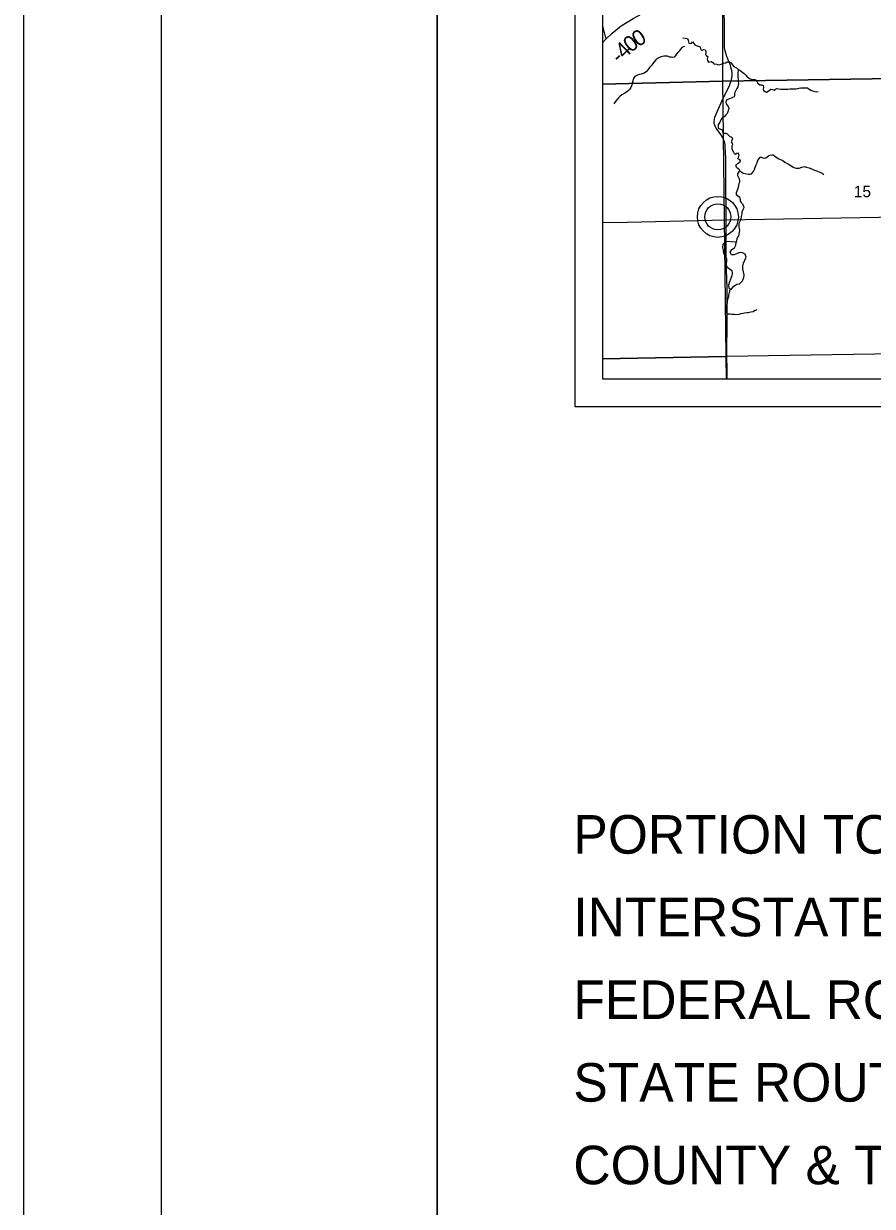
# Model space of a CAD drawing. Extents: x 0 to 34, y 0 to 22.
# Drawn here: x 0 to 3.079, y 11.097 to 15.389 of the extents above; entities that cross this region are included whole.
import ezdxf

# ---------------------------------------------------------------- set-up
doc = ezdxf.new("R2010")
doc.units = 0
for name, color, linetype in [('Default', 7, 'Continuous'), ('GM_X_County_Road', 7, 'Continuous'), ('GM_X_County_Road_Text', 7, 'Continuous'), ('GM_X_Minor_River', 7, 'Continuous'), ('GM_X_Rail_Line', 7, 'Continuous'), ('GM_X_Section', 7, 'Continuous'), ('GM_X_Section_Text', 7, 'Continuous'), ('GM_X_Township_Road', 7, 'Continuous'), ('GM_X_Unincorporated', 7, 'Continuous'), ('GM_X_Unincorporated_Location', 7, 'Continuous'), ('SH_Border', 7, 'Continuous'), ('SH_Cut_Line', 7, 'Continuous'), ('SH_Data', 7, 'Continuous'), ('SH_Text', 7, 'Continuous')]:
    doc.layers.add(name, color=color, linetype=linetype)

msp = doc.modelspace()

# ---------------------------------------------------------------- linework, layer by layer
at = {"layer": 'Default'}
for points in [[(2.1, 16.1599), (2.1, 15.1701), (2.5373, 15.181), (2.5362, 16.1651)], [(2.1, 15.1701), (2.1, 14.1728), (2.5493, 14.1808), (2.5373, 15.181)], [(2.1, 14.1728), (2.1, 14.1), (2.5497, 14.1), (2.5493, 14.1808)], [(2.5497, 14.1), (3.5508, 14.1), (3.5507, 14.1966), (2.5493, 14.1808)]]:
    msp.add_lwpolyline(points, close=True, dxfattribs=at)
at = {"layer": 'GM_X_County_Road'}
msp.add_lwpolyline([(2.1, 15.32), (2.1122, 15.3327), (2.1348, 15.3546), (2.1678, 15.3816), (2.2117, 15.4084), (2.3211, 15.4672), (2.3828, 15.501), (2.4511, 15.5376), (2.4613, 15.5442), (2.4683, 15.5476), (2.4745, 15.5517), (2.4853, 15.5591), (2.4974, 15.5707), (2.5116, 15.5851)], dxfattribs=at)
at = {"layer": 'GM_X_Minor_River'}
for points in [[(2.3917, 15.3375), (2.4089, 15.3348), (2.4116, 15.3295), (2.4117, 15.3238), (2.4134, 15.3185), (2.4183, 15.3171), (2.4232, 15.3184), (2.4273, 15.3234), (2.432, 15.3178), (2.4351, 15.3122), (2.4401, 15.3096), (2.447, 15.3071), (2.4531, 15.3068), (2.4559, 15.2997), (2.4572, 15.2944), (2.4621, 15.293), (2.4674, 15.295), (2.4731, 15.294), (2.4751, 15.2891), (2.4748, 15.2838), (2.4742, 15.2788), (2.4769, 15.2739), (2.482, 15.2706), (2.4813, 15.2653), (2.4803, 15.2603), (2.4811, 15.2554), (2.4847, 15.2498), (2.4896, 15.2503), (2.4949, 15.2515), (2.4999, 15.2486), (2.5038, 15.243), (2.5148, 15.2417), (2.5202, 15.2403), (2.5266, 15.2408), (2.5349, 15.2436), (2.5402, 15.2453), (2.5474, 15.2473), (2.553, 15.2501), (2.5602, 15.251), (2.5671, 15.2473), (2.5706, 15.2413), (2.5745, 15.2361), (2.5815, 15.2313), (2.5865, 15.2291), (2.593, 15.2232), (2.5984, 15.2199), (2.6049, 15.2162), (2.6146, 15.2081), (2.6208, 15.2021), (2.6251, 15.1961), (2.634, 15.1902), (2.6424, 15.1866), (2.6473, 15.186), (2.653, 15.1865), (2.658, 15.1843), (2.6643, 15.173), (2.6713, 15.1671), (2.6781, 15.1672), (2.6835, 15.1643), (2.6844, 15.1575), (2.6837, 15.1518), (2.6846, 15.1465), (2.69, 15.1432), (2.695, 15.141), (2.701, 15.1438), (2.7066, 15.1477), (2.7115, 15.1516), (2.7168, 15.1498), (2.7229, 15.1484), (2.7278, 15.1512), (2.7327, 15.1536), (2.7403, 15.1526), (2.746, 15.1516), (2.7543, 15.1518), (2.7597, 15.1515), (2.7729, 15.1518), (2.7794, 15.1523), (2.7877, 15.1521), (2.7972, 15.1527), (2.8025, 15.1531), (2.8124, 15.1549), (2.8192, 15.1558), (2.8264, 15.1559), (2.8313, 15.1564), (2.8385, 15.1566), (2.8442, 15.1559), (2.8504, 15.1519), (2.8562, 15.1482), (2.8619, 15.1453), (2.8669, 15.1439), (2.8779, 15.1418), (2.8828, 15.1427)], [(2.3979, 15.3064), (2.3935, 15.3056), (2.3883, 15.3028), (2.3838, 15.2974), (2.3801, 15.2924), (2.3772, 15.2874), (2.3716, 15.282), (2.3661, 15.2746), (2.3605, 15.2677), (2.3545, 15.266), (2.3495, 15.2671), (2.3427, 15.2681), (2.3358, 15.271), (2.3293, 15.2712), (2.3225, 15.2707), (2.3176, 15.2698), (2.3119, 15.2686), (2.3048, 15.2657), (2.2995, 15.2626), (2.2939, 15.2583), (2.2832, 15.2444), (2.278, 15.2375), (2.271, 15.2297), (2.2651, 15.2216), (2.2599, 15.2158), (2.2509, 15.2099), (2.24, 15.2055), (2.2347, 15.2043), (2.2268, 15.2022), (2.2174, 15.1974), (2.2122, 15.1901), (2.2095, 15.1779), (2.2081, 15.171), (2.2052, 15.163), (2.203, 15.1576), (2.199, 15.1518), (2.1942, 15.1464), (2.1875, 15.1402), (2.1815, 15.1367), (2.1702, 15.1311), (2.1631, 15.1253), (2.1587, 15.1195), (2.1524, 15.1129), (2.1464, 15.1055), (2.1409, 15.0978)], [(2.593, 15.2232), (2.5914, 15.2083), (2.5912, 15.2007), (2.591, 15.195), (2.5919, 15.1878), (2.5928, 15.1795), (2.5934, 15.1719), (2.5927, 15.1658), (2.591, 15.1597), (2.5873, 15.1543), (2.5793, 15.1374), (2.5787, 15.1287), (2.5773, 15.1233), (2.5724, 15.121), (2.5671, 15.119), (2.5551, 15.1138), (2.5491, 15.1102), (2.5477, 15.1041), (2.549, 15.0984), (2.5521, 15.0932), (2.5556, 15.0883), (2.5584, 15.0815), (2.5578, 15.0766), (2.5549, 15.0693), (2.5527, 15.0632), (2.5479, 15.0582), (2.542, 15.0516), (2.533, 15.0461), (2.5293, 15.0403), (2.5275, 15.0346), (2.5235, 15.0284), (2.5198, 15.0215), (2.5196, 15.0154), (2.5201, 15.0097), (2.5285, 15.0065), (2.5339, 15.0047), (2.5352, 14.9948), (2.5413, 14.9919), (2.5478, 14.9913), (2.5528, 14.9899), (2.5625, 14.9798), (2.5674, 14.9784), (2.5713, 14.9732), (2.5696, 14.9656), (2.5667, 14.9602), (2.5706, 14.9546), (2.5718, 14.9497), (2.57, 14.9447), (2.569, 14.9397), (2.5691, 14.9344), (2.5715, 14.9291), (2.575, 14.9231), (2.5774, 14.9175), (2.5824, 14.9153), (2.5873, 14.9196), (2.5922, 14.9201), (2.5938, 14.9144), (2.5943, 14.9095), (2.5925, 14.9045), (2.5907, 14.8992), (2.5965, 14.8974), (2.5993, 14.891), (2.5982, 14.886), (2.5926, 14.8821), (2.5844, 14.8774), (2.5841, 14.8709), (2.5888, 14.8657), (2.5946, 14.862), (2.5977, 14.8568), (2.5944, 14.8514), (2.5904, 14.8441), (2.5901, 14.8384), (2.5941, 14.8305), (2.5961, 14.8256), (2.597, 14.8195), (2.5967, 14.8142), (2.5953, 14.8092), (2.5925, 14.7959), (2.5904, 14.7879), (2.5875, 14.7813), (2.5854, 14.7752), (2.5851, 14.7695), (2.5905, 14.7655), (2.5967, 14.7599), (2.5992, 14.7508), (2.6, 14.7455), (2.6032, 14.7399), (2.6086, 14.7354), (2.6122, 14.7264), (2.6127, 14.7211), (2.6087, 14.7111), (2.6062, 14.7043), (2.6052, 14.6989), (2.6049, 14.694), (2.6039, 14.689), (2.6025, 14.6814), (2.5997, 14.6733), (2.5949, 14.6641), (2.5947, 14.6565), (2.5948, 14.6508), (2.5964, 14.6459)], [(2.5977, 14.8568), (2.6104, 14.8472), (2.6184, 14.8454), (2.6291, 14.8434), (2.6356, 14.8424), (2.6405, 14.8444), (2.6479, 14.8529), (2.6515, 14.8602), (2.6536, 14.8682), (2.658, 14.8766), (2.6609, 14.8843), (2.6627, 14.8897), (2.6663, 14.8962), (2.6718, 14.905), (2.6768, 14.9051), (2.6825, 14.9018), (2.6875, 14.9008), (2.6924, 14.9024), (2.7025, 14.9095), (2.7074, 14.9119), (2.7142, 14.9131), (2.7195, 14.9129), (2.7299, 14.9047), (2.7399, 14.8981), (2.7457, 14.8963), (2.7549, 14.892), (2.7622, 14.8864), (2.7699, 14.8813), (2.7776, 14.8776), (2.7833, 14.8743), (2.7918, 14.8684), (2.7983, 14.8655), (2.8033, 14.8645), (2.8086, 14.8646), (2.8139, 14.8651), (2.8229, 14.8683), (2.8286, 14.87), (2.8347, 14.8705), (2.8396, 14.8687), (2.8503, 14.8655), (2.8695, 14.8575), (2.8802, 14.8536), (2.8917, 14.8489), (2.8974, 14.846), (2.9036, 14.8423)], [(2.5964, 14.6459), (2.597, 14.6387), (2.596, 14.6319), (2.5932, 14.6189), (2.5903, 14.6139), (2.5874, 14.6085), (2.5851, 14.5956)], [(2.5834, 14.5961), (2.5459, 14.5989), (2.5367, 14.588), (2.5359, 14.5774), (2.5374, 14.5671), (2.5392, 14.5565), (2.5452, 14.5469), (2.5505, 14.5374), (2.5504, 14.5279), (2.5492, 14.5173), (2.5499, 14.5078), (2.5597, 14.5005), (2.57, 14.4932), (2.571, 14.4837), (2.5698, 14.4743), (2.5644, 14.4622), (2.5605, 14.4519), (2.5574, 14.4406), (2.5581, 14.43), (2.5676, 14.4246), (2.5764, 14.4363), (2.5879, 14.4438)], [(2.5879, 14.4438), (2.5974, 14.4448), (2.6081, 14.4561), (2.6124, 14.4675), (2.614, 14.4773), (2.6099, 14.4994), (2.6096, 14.5092), (2.6116, 14.5199), (2.617, 14.5308), (2.6209, 14.5422), (2.6179, 14.5528), (2.608, 14.5575), (2.5985, 14.5583), (2.5886, 14.5549), (2.5783, 14.5497), (2.5684, 14.5498), (2.5639, 14.5593), (2.5697, 14.5691), (2.5793, 14.5759), (2.5843, 14.5857), (2.5851, 14.5956), (2.5834, 14.5961)], [(2.5631, 14.4265), (2.561, 14.4191), (2.5572, 14.4031), (2.5569, 14.3977), (2.5544, 14.3916), (2.553, 14.3828), (2.5528, 14.376), (2.5499, 14.368), (2.5489, 14.3626), (2.5486, 14.3569), (2.5489, 14.3448), (2.5505, 14.3387), (2.5555, 14.3365), (2.5631, 14.3359), (2.5692, 14.3349), (2.5791, 14.3348), (2.5841, 14.3341), (2.5958, 14.3351), (2.6037, 14.3372), (2.6105, 14.3385), (2.6154, 14.3397), (2.6238, 14.3406), (2.6291, 14.3408), (2.6385, 14.3429), (2.6472, 14.3449), (2.6521, 14.3481), (2.657, 14.3493), (2.6619, 14.3517)]]:
    msp.add_lwpolyline(points, dxfattribs=at)
at = {"layer": 'GM_X_Rail_Line'}
msp.add_lwpolyline([(2.1, 17.2107), (2.1, 14.1), (5.5619, 14.1), (5.5608, 14.205), (5.5615, 14.2414), (5.5595, 14.6439), (5.5583, 14.9347), (5.5581, 14.9676), (5.5588, 15.1747), (5.5579, 15.2049), (4.0847, 15.1965), (3.5411, 15.1931), (3.5298, 15.9318), (3.5269, 16.3549), (3.511, 17.2267), (3.4711, 17.2262), (2.9494, 17.2203), (2.5218, 17.2155)], close=True, dxfattribs=at)
at = {"layer": 'GM_X_Section'}
for points in [[(2.5362, 16.1651), (3.5333, 16.1865), (3.5436, 15.1965), (2.5373, 15.181)], [(2.5373, 15.181), (3.5436, 15.1965), (3.5507, 14.1966), (2.5493, 14.1808)]]:
    msp.add_lwpolyline(points, close=True, dxfattribs=at)
at = {"layer": 'GM_X_Township_Road'}
for points in [[(2.5096, 15.015), (2.5073, 15.0203), (2.5058, 15.0274), (2.5054, 15.0335), (2.5063, 15.0423), (2.5077, 15.0497), (2.5113, 15.0585), (2.5384, 15.1183), (2.5605, 15.1635), (2.5651, 15.1753), (2.5674, 15.1822), (2.5696, 15.192), (2.5708, 15.2025), (2.5708, 15.2105), (2.5689, 15.2189), (2.5672, 15.2262), (2.5646, 15.2372), (2.5617, 15.2444), (2.5591, 15.252), (2.5553, 15.262), (2.5517, 15.27), (2.5475, 15.2824), (2.5448, 15.2907), (2.543, 15.3015), (2.5423, 15.3193), (2.5434, 15.3652), (2.541, 15.5446)], [(2.1, 15.3803), (2.1008, 15.3771), (2.1122, 15.3327)], [(2.1, 14.6671), (2.19, 14.6684), (2.5484, 14.6774), (3.1035, 14.6866), (3.1904, 14.6884), (3.5595, 14.6939), (3.8262, 14.9464), (3.8356, 14.9553), (3.8461, 14.9638), (3.855, 14.9715), (3.8812, 14.9962), (3.8946, 15.0105), (3.9125, 15.0298), (3.9618, 15.0811), (3.9775, 15.0976), (4.0171, 15.1332), (4.0644, 15.171)], [(2.5484, 14.6774), (2.5479, 14.8271), (2.5482, 14.8961), (2.5468, 14.9267), (2.5458, 14.94), (2.5448, 14.9486), (2.5436, 14.9567), (2.5425, 14.962), (2.5404, 14.9669), (2.5384, 14.9719), (2.5356, 14.9776), (2.532, 14.9838), (2.5275, 14.9907), (2.5184, 15.0015), (2.5125, 15.0098), (2.5096, 15.015)], [(2.5524, 14.1), (2.5524, 14.1102), (2.5524, 14.1375), (2.5512, 14.1776), (2.5528, 14.32), (2.552, 14.4291), (2.5504, 14.4961), (2.5488, 14.5755), (2.5484, 14.6774)]]:
    msp.add_lwpolyline(points, dxfattribs=at)
at = {"layer": 'GM_X_Unincorporated'}
for radius in [0.0744, 0.0472]:
    msp.add_circle((2.5187, 14.6881), radius, dxfattribs=at)
at = {"layer": 'GM_X_Unincorporated_Location'}
msp.add_line((2.5187, 14.6881), (2.5187, 14.6881), dxfattribs=at)
at = {"layer": 'SH_Border'}
for points in [[(0.5, 21.5), (1.5, 21.5), (1.5, 0.5), (0.5, 0.5)], [(1.5, 21.5), (33.5, 21.5), (33.5, 0.5), (1.5, 0.5)]]:
    msp.add_lwpolyline(points, close=True, dxfattribs=at)
at = {"layer": 'SH_Cut_Line'}
msp.add_lwpolyline([(0, 0), (34, 0), (34, 22), (0, 22)], close=True, dxfattribs=at)
msp.add_lwpolyline([(2.1, 17.2107), (2.1, 14.1), (8.9, 14.1)], dxfattribs=at)
at = {"layer": 'SH_Data'}
for p, q in [((2, 21), (2, 14)), ((2.1, 20.9), (2.1, 14.1)), ((2.1, 14.1), (8.9, 14.1)), ((2.1, 14.1), (2.1, 14.1)), ((2, 14), (9, 14))]:
    msp.add_line(p, q, dxfattribs=at)

# ---------------------------------------------------------------- texts
at = {"layer": 'GM_X_County_Road_Text'}
for s, rotation, p in [('0', 32.2365, (2.2292, 15.303)), ('0', 38.2876, (2.203, 15.2822)), ('4', 44.0726, (2.179, 15.2588)), ('-', 44.8344, (2.1626, 15.2425))]:
    msp.add_text(s, height=0.0568, rotation=rotation, dxfattribs=at).set_placement(p)
at = {"layer": 'GM_X_Section_Text'}
msp.add_text('15', height=0.04186, rotation=0, dxfattribs=at).set_placement((3.0122, 14.7594))
at = {"layer": 'SH_Text'}
for s, p in [('PORTION TO BE IMPROVED', (1.9944, 12.3767)), ('INTERSTATE HIGHWAY', (1.9944, 12.0767)), ('FEDERAL ROUTES', (1.9944, 11.7767)), ('STATE ROUTES', (1.9944, 11.4767)), ('COUNTY & TOWNSHIP ROADS', (1.9944, 11.1767))]:
    msp.add_text(s, height=0.14, dxfattribs=at).set_placement(p)

doc.saveas('drawing.dxf')
